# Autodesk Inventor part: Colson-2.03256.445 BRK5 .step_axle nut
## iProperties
Created: 2010-10
Part Number: Colson-2.03256.445 BRK5 .step_axle nut
Document SubType Name: Modeling
Designer: Administrator
Density: 7.85 g/cm^3
Material: Steel
Mass: 4.83938 g
Surface Area: 6.79431 cm^2
Volume: 0.616482 cm^3
Author: Administrator
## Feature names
1. Base1
